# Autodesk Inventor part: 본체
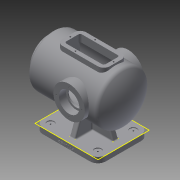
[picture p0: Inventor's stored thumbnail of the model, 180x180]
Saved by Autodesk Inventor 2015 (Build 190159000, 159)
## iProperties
Created: 2021-11
Part Number: 본체
Material: 일반
Document SubType Name: Modeling
Designer: 1016549
Density: 1 g/cm^3
Appearance: 기본값
Author: 1016549
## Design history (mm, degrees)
sketch "스케치1"
  geometry: C1 r 65 at (0, 0); 1 further point
  constraints: 1 centre point, 1 coincident
  dimensions: "d0" = 130 diameter of C1
extrude "돌출1" new body sketch "스케치1" stored distance "d1" = 200; taper "d2" = 0 deg
sketch "스케치2"
  geometry: L1 (100, 65)-(100, -65) reference; L2 (100, -65)-(-100, -65) reference; L3 (-100, -65)-(-100, 65) reference; L4 (-100, 65)-(100, 65) reference; L5 (100, 0)-(-100, 0); A1 r 100 centre (0, 0) between (-75.993, 65) and (-100, 0); 1 further point
  constraints: 3 midpoint, 2 end point, 2 point on circle, 1 centre point, 1 horizontal, 1 point on line
  dimensions: "d3" = 100 radius of A1
revolve "회전1" sketch "스케치2" stored, may be unused: angle "d4" = 90 deg
fillet "모깎기1" dims "d5" = 10
feature "쉘1" dims "d6" = 10
sketch "스케치3"
  geometry: C1 r 55 at (0, 0) reference; C2 r 65 at (0, 0) reference; C3 r 65 at (0, 0)
  constraints: 1 centre point, 1 coincident, 1 concentric
extrude "돌출2" join sketch "스케치3" distance "d7" = 15; taper "d8" = 0 deg
sketch "스케치4"
  geometry: C1 r 65 at (0, 0) reference; C2 r 47.5 at (0, 0)
  constraints: 1 centre point, 1 coincident
  dimensions: "d9" = 95 diameter of C2
extrude "돌출3" join sketch "스케치4" distance "d10" = 10; taper "d11" = 0 deg
sketch "스케치5"
  geometry: C1 r 47.5 at (0, 0) reference
hole "구멍1" sketch "스케치5" at (0, 0) diameter "d12" = 65; stored, may be unused: countersink angle "d16" = 90 deg, drill point angle "d18" = 118 deg; dims "d13" = 6, "d14" = 4, "d15" = 2, "d17" = 30
fillet "모깎기2" dims "d19" = 10
sketch "스케치6"
  geometry: 1 further point
node "작업 평면2"
sketch "스케치7"
  geometry: L1 (-80, -65)-(80, -65); L2 (80, -65)-(80, 65); L3 (80, 65)-(-80, 65); L4 (-80, 65)-(-80, -65); 3 further points
  constraints: 8 end point, 2 midpoint, 2 parallel, 1 horizontal, 1 horizontal alignment, 1 perpendicular, 1 vertical alignment
  dimensions: "d22" = 130 distance of L1.end L2.end; "d23" = 160 distance of L2.end L3.end
extrude "돌출4" join sketch "스케치7" distance "d24" = 14; taper "d25" = 0 deg
sketch "스케치8"
  geometry: L1 (60, -7)-(-60, -7); L2 (-60, -7)-(-60, 7); L3 (-60, 7)-(60, 7); L4 (60, 7)-(60, -7); L5 (60, -7)-(-60, 7); L6 (-60, -7)-(60, 7); L7 (7, -50)-(-7, -50); L8 (-7, -50)-(-7, 50); L9 (-7, 50)-(7, 50); L10 (7, 50)-(7, -50); L11 (7, -50)-(-7, 50); L12 (-7, -50)-(7, 50); 1 further point
  constraints: 24 end point, 4 midpoint, 4 parallel, 2 horizontal, 2 perpendicular
  dimensions: "d28" = 120 distance of L1.start L1.end; "d29" = 14 distance of L3.end L1.start; "d30" = 14 distance of L8.end L9.end; "d31" = 100 distance of L9.end L7.start
extrude "돌출5" join sketch "스케치8" stored distance "d26" = 14; taper "d27" = 0 deg
sketch "스케치9"
  geometry: L1 (60, -7)-(7, -7) reference; L2 (7, -7)-(7, -50) reference; L3 (7, -50)-(-7, -50) reference; L4 (-7, -50)-(-7, -7) reference; L5 (-7, -7)-(-60, -7) reference; L6 (-60, -7)-(-60, 7) reference; L7 (-60, 7)-(-7, 7) reference; L8 (-7, 7)-(-7, 50) reference; L9 (-7, 50)-(7, 50) reference; L10 (7, 50)-(7, 7) reference; L11 (7, 7)-(60, 7) reference; L12 (60, 7)-(60, -7) reference; L13 (-80, -65)-(80, -65) reference; L14 (80, -65)-(80, 65) reference; L15 (80, 65)-(-80, 65) reference; L16 (-80, 65)-(-80, -65) reference; 1 further point
feature "면 기울기1" dims angle "d32" = 20 deg
feature "면 기울기2" dims angle "d33" = 20 deg
feature "면 기울기3" dims angle "d34" = 20 deg
feature "면 기울기4" dims angle "d35" = 20 deg
node "작업 평면3"
sketch "스케치10"
  geometry: L1 (110, -47.5)-(110, 47.5) reference; C1 r 40 at (-17, 0); 2 further points
  constraints: 1 centre point, 1 coincident, 1 horizontal alignment, 1 midpoint
  dimensions: "d112" = 127 distance from line of point (-17, 0) L1
extrude "돌출6" join sketch "스케치10" stored distance "d38" = 14; taper "d39" = 0 deg
node "작업 평면4"
sketch "스케치11"
  geometry: L1 (-60, 30)-(60, 30); L2 (60, 30)-(60, -30); L3 (60, -30)-(-60, -30); L4 (-60, -30)-(-60, 30); L5 (-110, 47.5)-(-110, -47.5) reference; 2 further points
  constraints: 8 end point, 2 parallel, 1 horizontal, 1 horizontal alignment, 1 midpoint, 1 perpendicular
  dimensions: "d41" = 60 distance of L1.end L2.end; "d42" = 120 distance of L2.end L3.end; "d113" = 50 distance between parallel lines of L4 L5
extrude "돌출7" join sketch "스케치11" stored distance "d44" = 14; taper "d45" = 0 deg
fillet "모깎기3" dims "d46" = 15
sketch "스케치12"
  geometry: L1 (-45, 30)-(45, 30) reference; L2 (-60, -15)-(-60, 15) reference; L3 (45, -30)-(-45, -30) reference; L4 (60, 15)-(60, -15) reference; L5 (50, 15)-(50, -15); L6 (45, -20)-(-45, -20); L7 (-50, -15)-(-50, 15); L8 (-45, 20)-(45, 20); A1 r 15 centre (45, 15) between (60, 15) and (45, 30) reference; A2 r 15 centre (-45, 15) between (-45, 30) and (-60, 15) reference; A3 r 15 centre (-45, -15) between (-60, -15) and (-45, -30) reference; A4 r 15 centre (45, -15) between (45, -30) and (60, -15) reference; A5 r 5 centre (45, 15) between (50, 15) and (45, 20); A6 r 5 centre (45, -15) between (45, -20) and (50, -15); A7 r 5 centre (-45, -15) between (-50, -15) and (-45, -20); A8 r 5 centre (-45, 15) between (-45, 20) and (-50, 15); 1 further point
  constraints: 8 end point, 8 point on circle, 4 centre point, 7 other
  dimensions: "d47" = 10 distance between parallel lines of L1 L8
extrude "돌출8" cut sketch "스케치12" distance "d48" = 20; taper "d49" = 0 deg
sketch "스케치13"
  geometry: 1 further point
sketch "스케치14"
  geometry: L1 (-127, 47.5)-(-127, -47.5) reference; C1 r 40 at (0, 0)
  constraints: 1 centre point
  dimensions: "d111" = 127 distance from line of C1.centre L1
hole "구멍2" sketch "스케치14" at (0, 0) diameter "d50" = 42; stored, may be unused: countersink angle "d54" = 90 deg, drill point angle "d56" = 118 deg; dims "d51" = 6, "d52" = 52, "d53" = 18, "d55" = 30
sketch "스케치16"
  geometry: C1 r 26 at (0, 0) reference; 1 further point
  constraints: 1 vertical alignment
  dimensions: "d57" = 32.5 distance of C1.centre point (0, 32.5)
hole "구멍3" sketch "스케치16" at (0, 32.5) diameter "d58" = 3.242; stored, may be unused: countersink angle "d62" = 90 deg, drill point angle "d64" = 118 deg; dims "d59" = 11, "d60" = 52, "d61" = 18, "d63" = 13
sketch "스케치17"
  geometry: C1 r 32.5 at (0, 0) reference; 1 further point
  constraints: 1 horizontal alignment
  dimensions: "d68" = 40 distance of C1.centre point (40, 0)
hole "구멍4" sketch "스케치17" at (40, 0) diameter "d69" = 3.242; stored, may be unused: countersink angle "d73" = 90 deg, drill point angle "d75" = 118 deg; dims "d70" = 11, "d71" = 52, "d72" = 18, "d74" = 13
sketch "스케치18"
  geometry: 2 further points
  dimensions: "d79" = 17 horizontal distance of point (-17, 25) point (0, 0); "d80" = 25 vertical distance of point (-17, 25) point (0, 0)
hole "구멍5" sketch "스케치18" at (-17, 25) diameter "d81" = 3.242; stored, may be unused: countersink angle "d85" = 90 deg, drill point angle "d87" = 118 deg; dims "d82" = 9, "d83" = 52, "d84" = 18, "d86" = 11
sketch "스케치19"
  geometry: C1 r 1.621 at (-17, 25) reference; 3 further points
  constraints: 2 horizontal alignment
  dimensions: "d89" = 55 horizontal distance of point (38, 0) C1.centre; "d114" = 55 distance of point (-55, 0) point (0, 0)
hole "구멍6" sketch "스케치19" at (-55, 0), (38, 0) diameter "d90" = 3.242; stored, may be unused: countersink angle "d94" = 90 deg, drill point angle "d96" = 118 deg; dims "d91" = 9, "d92" = 52, "d93" = 18, "d95" = 11
fillet "모깎기4" dims "d97" = 20
sketch "스케치20"
  geometry: A1 r 20 centre (60, 45) between (80, 45) and (60, 65) reference; A2 r 20 centre (-60, 45) between (-60, 65) and (-80, 45) reference; A3 r 20 centre (-60, -45) between (-80, -45) and (-60, -65) reference; A4 r 20 centre (60, -45) between (60, -65) and (80, -45) reference; 1 further point
hole "구멍7" sketch "스케치20" at (-60, -45), (-60, 45), (60, 45), (60, -45) diameter "d98" = 3.242; stored, may be unused: countersink angle "d102" = 90 deg, drill point angle "d104" = 118 deg; dims "d99" = 9, "d100" = 18, "d101" = 2, "d103" = 11
fillet "모깎기5" dims "d105" = 3
fillet "모깎기6" dims "d106" = 3
fillet "모깎기7" dims "d107" = 3
sketch "스케치21"
  geometry: L1 (0, 0)-(120, 0) reference; 3 further points
  constraints: 1 midpoint, 1 vertical alignment, 1 other
  dimensions: "d108" = 5 distance from line of L1 point (60, 5)
feature "엠보싱1" sketch "스케치21" dims "d109" = 0.5, "d110" = 0
node "작업 평면5"
node "솔리드1"
mirror "대칭1"
mirror "대칭2"
pattern_circular "원형 패턴1" dims angle "d66" = 360 deg
mirror "대칭3"
pattern_circular "원형 패턴2" dims angle "d77" = 360 deg
mirror "대칭4"
mirror "대칭5"
node "절단 모서리 투영1"
other parameters: "d21" = -114, "d36" = -75
